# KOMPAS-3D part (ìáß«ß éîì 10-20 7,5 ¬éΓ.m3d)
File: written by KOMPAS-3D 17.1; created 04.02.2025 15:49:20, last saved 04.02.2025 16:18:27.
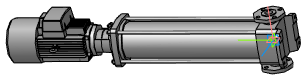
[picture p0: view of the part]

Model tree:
1. Операция без истории:1  (labels: Насос ВМН 10-20 7,5 кВт)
